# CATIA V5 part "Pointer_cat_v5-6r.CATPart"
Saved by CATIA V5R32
Part number: Pointer
Bounding box of the stored display mesh (mm): x -9.942 to 9.942, y -9.942 to 9.942, z 0 to 100
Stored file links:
  D:\PROJECTS\Project 2022\CATIA V5 6R 2022\Resources\Tutorial Files\c16_catia_v5_6r2022_tut\Cam Follower mechanism\Pointer_cat_v5-6r.CATPart
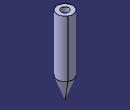
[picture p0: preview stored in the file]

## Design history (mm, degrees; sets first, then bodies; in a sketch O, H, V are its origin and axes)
Body1 (main body)
  Sketch1 on yz-plane, origin (0, 0, 0), H (0, 1, 0), V (0, 0, 1)
    line L1 (0, 0) -> (10, 27.4748)
    point P1 (10, 27.4748)
    line L2 (10, 27.4748) -> (10, 100)
    point P2 (10, 27.4748)
    point P3 (10, 100)
    point P4 (0, 100)
    point P5 (10, 91.3901)
    line L3 (0, 0) -> (0, 100)
    reference intersected line E1 through (0, 0) direction (-1, 0) from xy-plane
    reference intersected line E3 through (0, 0) direction (0, 1) from zx-plane
    line L4 (0, 100) -> (10, 100)
    point P6 (10, 100)
    angle L1 L3 = 20
    distance O P4 = 100
    length L4 = 10
    coincidence: P2 L1, P4 V, P5 L2, P2 P1, E3 P4, P1 L2, P6 L2, P6 P3
    vertical: L2 V, L3 V, E3 V
    horizontal: E1 H, L4 H
    perpendicularity: E1 L2
  Shaft1: profile Sketch1, axis Sketch1.L3, angle 360
  Sketch2 on face of Shaft1 from Sketch1.L4, origin (0, 0, 100), H (1, 0, 0), V (0, 1, 0)
    point P1 (0, 0)
  Hole1: placed by Sketch2, at (0, 0, 100) direction (0, 0, -1), diameter 10, depth 55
